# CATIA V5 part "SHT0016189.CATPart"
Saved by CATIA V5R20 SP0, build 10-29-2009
Part number: SHT0016189
Bounding box of the stored display mesh (mm): x -154 to 21.394, y -791.417 to -526.592, z 87.8 to 106.4
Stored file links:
  F:\福田A6\1-数据\6-冻结数据\第九批\设变\静电导线设变\SHT0015987 中宽车底部支架焊接总成\改后数据\SHT0016189-中宽车主驾驶后侧钣金\SHT0016189.CATPart

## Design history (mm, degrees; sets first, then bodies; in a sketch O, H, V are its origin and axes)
Set1
  DatumCurve1 to DatumCurve5
  DatumSurface1
  DatumCurve6 to DatumCurve11
  DatumSurface2
  DatumCurve12
Body1 (main body)
Body2 "SHT0016189-中宽车主驾驶后侧钣金"
  Solid1: solid without history
  Sketch1 on face of Solid1, origin (0, 0, 106.4), H (1, 0, 0), V (0, 1, 0)
    line L1 (-123.4942, -535.3701) -> (-38.3172, -535.3701)
    line L2 (-38.3172, -535.3701) -> (-38.3172, -552.7477)
    line L3 (-38.3172, -552.7477) -> (-123.4942, -552.7477)
    line L4 (-123.4942, -552.7477) -> (-123.4942, -535.3701)
    line L5 (-123.1528, -766.3473) -> (-34.3512, -766.3473)
    line L6 (-34.3512, -766.3473) -> (-34.3512, -782.6388)
    line L7 (-34.3512, -782.6388) -> (-123.1528, -782.6388)
    line L8 (-123.1528, -782.6388) -> (-123.1528, -766.3473)
    line L9 (-42.3253, -700.8193) -> (-25.2899, -700.8193)
    line L10 (-25.2899, -700.8193) -> (-25.2899, -719.645)
    line L11 (-25.2899, -719.645) -> (-42.3253, -719.645)
    line L12 (-42.3253, -719.645) -> (-42.3253, -700.8193)
    horizontal: L1 H, L3 H, L5 H, L7 H, L9 H, L11 H
    vertical: L2 V, L4 V, L6 V, L8 V, L10 V, L12 V
  Pad1: profile Sketch1, direction (0, 0, 1), up to face of Solid1
  Sketch2 on face of Solid1, origin (-131.7794, -778.9727, 106.4), H (1, 0, 0), V (0, 1, 0)
    point P1 (15.4244, 4.9732)
    reference projected arc E1 centre (15.4244, 4.9732) radius 4.5 from (19.9244, 4.9732) to (10.9244, 4.9732) ccw from edge of DatumCurve1
    concentricity: P1 E1
  Hole1: placed by Sketch2, at (-116.3549, -773.9995, 106.4) direction (0, 0, -1), diameter 9, depth 10
  Sketch3 on face of Solid1, origin (-77.4933, -772.1052, 106.4), H (1, 0, 0), V (0, 1, 0)
    point P1 (26.1384, -1.8943)
    reference projected arc E1 centre (26.1384, -1.8943) radius 4.5 from (30.6384, -1.8943) to (21.6384, -1.8943) ccw from edge of DatumCurve2
    concentricity: P1 E1
  Hole2: placed by Sketch3, at (-51.3549, -773.9995, 106.4) direction (0, 0, -1), diameter 9, depth 10
  Sketch4 on face of Solid1, origin (-107.2032, -540.4053, 106.4), H (1, 0, 0), V (0, 1, 0)
    point P1 (-9.1517, -3.5942)
    reference projected arc E1 centre (-9.1517, -3.5942) radius 4.5 from (-4.6517, -3.5942) to (-13.6517, -3.5942) ccw from edge of DatumCurve4
    concentricity: P1 E1
  Hole3: placed by Sketch4, at (-116.3549, -543.9995, 106.4) direction (0, 0, -1), diameter 9, depth 10
  Sketch5 on face of Solid1, origin (-61.1199, -546.4932, 106.4), H (1, 0, 0), V (0, 1, 0)
    point P1 (9.7649, 2.4937)
    reference projected arc E1 centre (9.7649, 2.4937) radius 4.5 from (14.2649, 2.4937) to (5.2649, 2.4937) ccw from edge of DatumCurve5
    concentricity: P1 E1
  Hole4: placed by Sketch5, at (-51.3549, -543.9995, 106.4) direction (0, 0, -1), diameter 9, depth 10
  Sketch6 on face of Solid1, origin (-33.2957, -687.0029, 106.4), H (1, 0, 0), V (0, 1, 0)
    point P1 (0.5999, -23.335)
    reference projected arc E1 centre (0.5999, -23.335) radius 3.5 from (3.7622, -21.835) to (-2.4716, -21.657) ccw from edge of DatumCurve7
    concentricity: P1 E1
  Hole5: placed by Sketch6, at (-32.6958, -710.338, 106.4) direction (0, 0, -1), diameter 7, depth 10
  Sketch7 on face of Solid1, origin (0, 0, 106.4), H (1, 0, 0), V (0, 1, 0)
    point P1 (-26.1958, -708.838)
    projected line E1 (-26.1958, -711.838) -> (-26.1958, -708.838) from edge of DatumCurve9
    point P2 (-26.1958, -711.838)
    point P3 (-26.1958, -708.838)
    point P5 (-26.1958, -711.838)
    line L1 (-26.1958, -708.838) -> (-31.4781, -708.838)
    line L2 (-31.2296, -711.838) -> (-26.1958, -711.838)
    line L3 (-31.4781, -708.838) -> (-31.2296, -711.838)
    fix: L1, L2
    coincidence: P1 P3, P2 P5
  Pocket1: profile Sketch7, direction (0, 0, -1), length 20
  Sketch8 on face of Solid1, origin (0, 0, 106.4), H (1, 0, 0), V (0, 1, 0)
    circle A1 centre (-39, -605.9995) radius 4.5
    reference projected arc E1 centre (-39, -605.9995) radius 4.5 from (-35.0509, -608.1569) to (-42.9491, -603.8421) ccw from edge of DatumCurve12
    radius A1 = 4.5
    concentricity: E1 A1
  Pocket2: profile Sketch8, direction (0, 0, -1), length 20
